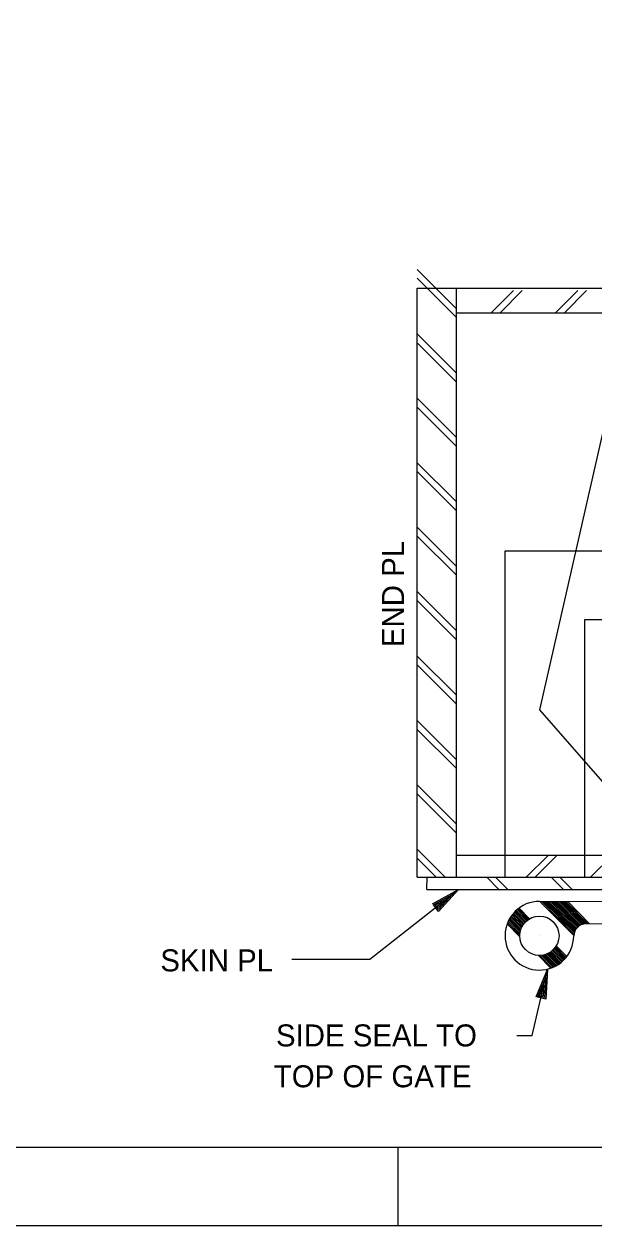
# Model space of a CAD drawing. Extents: x 0.1 to 13.5, y 0.1 to 9.5.
# Drawn here: x 7.414 to 8.625, y 0.125 to 2.675 of the extents above; entities that cross this region are included whole.
import ezdxf

# ---------------------------------------------------------------- set-up
doc = ezdxf.new("R2010")
doc.units = 0
for name, color, linetype in [('Level 0', 7, 'Continuous'), ('Level 1', 7, 'Continuous'), ('Level 13', 7, 'Continuous'), ('Level 25', 7, 'Continuous'), ('Level 3', 7, 'Continuous'), ('Level 50', 7, 'Continuous')]:
    doc.layers.add(name, color=color, linetype=linetype)

msp = doc.modelspace()

# ---------------------------------------------------------------- linework, layer by layer
at = {"layer": 'Level 0'}
for p, q in [((8.3325, 2.0711), (8.2492, 2.1544)), ((8.3325, 2.0522), (8.2492, 2.1356)), ((8.4066, 2.0626), (8.4535, 2.1095)), ((8.4254, 2.0626), (8.4723, 2.1095)), ((8.5433, 2.0626), (8.5902, 2.1095)), ((8.5621, 2.0626), (8.6091, 2.1095)), ((8.3325, 1.9344), (8.2492, 2.0177)), ((8.3325, 1.9155), (8.2492, 1.9989)), ((8.3325, 1.7977), (8.2492, 1.881)), ((8.3325, 1.7788), (8.2492, 1.8622)), ((8.3325, 1.661), (8.2492, 1.7443)), ((8.3325, 1.6421), (8.2492, 1.7255)), ((8.3325, 1.5243), (8.2492, 1.6076)), ((8.3325, 1.5054), (8.2492, 1.5888)), ((8.3325, 1.3876), (8.2492, 1.4709)), ((8.3325, 1.3687), (8.2492, 1.452)), ((8.3325, 1.2509), (8.2492, 1.3342)), ((8.3325, 1.232), (8.2492, 1.3153)), ((8.3325, 1.1141), (8.2492, 1.1975)), ((8.3325, 1.0953), (8.2492, 1.1786)), ((8.3325, 0.9774), (8.2492, 1.0608)), ((8.3325, 0.9586), (8.2492, 1.0419)), ((8.3086, 0.8647), (8.2492, 0.9241)), ((8.2897, 0.8647), (8.2492, 0.9052)), ((8.481, 0.8647), (8.5279, 0.9115)), ((8.4999, 0.8647), (8.5467, 0.9115)), ((8.6177, 0.8647), (8.6646, 0.9115)), ((8.423, 0.8387), (8.397, 0.8647)), ((8.4419, 0.8387), (8.4159, 0.8647)), ((8.5597, 0.8387), (8.5337, 0.8647)), ((8.5786, 0.8387), (8.5526, 0.8647))]:
    msp.add_line(p, q, dxfattribs=at)
at = {"layer": 'Level 1'}
msp.add_line((8.2083, 0.2917), (8.2083, 0.125), dxfattribs=at)
for points in [[(0.125, 9.4583), (13.4583, 9.4583), (13.4583, 0.125), (0.125, 0.125)], [(0.625, 9.2917), (13.2917, 9.2917), (13.2917, 0.2917), (0.625, 0.2917)]]:
    msp.add_lwpolyline(points, close=True, dxfattribs=at)
at = {"layer": 'Level 13'}
for p, q in [((8.4558, 0.7909), (8.4777, 0.7686)), ((8.4577, 0.7927), (8.4796, 0.7704)), ((8.4596, 0.7944), (8.4815, 0.7722)), ((8.4615, 0.7962), (8.4835, 0.7738)), ((8.4635, 0.7979), (8.4857, 0.7754)), ((8.4656, 0.7995), (8.4879, 0.7768)), ((8.9261, 0.8105), (8.5094, 0.8137)), ((8.5101, 0.8136), (8.5818, 0.7409)), ((8.5138, 0.8136), (8.5821, 0.7442)), ((8.5175, 0.8136), (8.5828, 0.7473)), ((8.5211, 0.8136), (8.5838, 0.75)), ((8.5248, 0.8135), (8.5849, 0.7525)), ((8.5285, 0.8135), (8.5861, 0.755)), ((8.5322, 0.8135), (8.588, 0.7569)), ((8.5359, 0.8135), (8.5899, 0.7587)), ((8.5396, 0.8134), (8.5917, 0.7605)), ((8.5432, 0.8134), (8.5939, 0.762)), ((8.5469, 0.8134), (8.5962, 0.7633)), ((8.5506, 0.8133), (8.5988, 0.7644)), ((8.5543, 0.8133), (8.6016, 0.7653)), ((8.558, 0.8133), (8.6047, 0.7658)), ((8.5617, 0.8133), (8.6082, 0.766)), ((8.5653, 0.8132), (8.6118, 0.766)), ((8.569, 0.8132), (8.6155, 0.766)), ((8.4403, 0.7657), (8.4672, 0.7384)), ((8.4414, 0.7684), (8.4672, 0.7422)), ((8.4425, 0.771), (8.4674, 0.7456)), ((8.4437, 0.7735), (8.468, 0.7488)), ((8.445, 0.7759), (8.4687, 0.7518)), ((8.4463, 0.7782), (8.4696, 0.7546)), ((8.4477, 0.7805), (8.4706, 0.7573)), ((8.4492, 0.7827), (8.4718, 0.7598)), ((8.4508, 0.7848), (8.4731, 0.7621)), ((8.4524, 0.7869), (8.4743, 0.7647)), ((8.4541, 0.7889), (8.4761, 0.7665)), ((8.9257, 0.7636), (8.608, 0.766)), ((8.5416, 0.7149), (8.5636, 0.6926)), ((8.5431, 0.717), (8.565, 0.6948)), ((8.5446, 0.7193), (8.5669, 0.6966)), ((8.5059, 0.6992), (8.5328, 0.6719)), ((8.5097, 0.6991), (8.5355, 0.6728)), ((8.5131, 0.6993), (8.5381, 0.6739)), ((8.5163, 0.6997), (8.5406, 0.6751)), ((8.5193, 0.7004), (8.543, 0.6763)), ((8.5221, 0.7012), (8.5454, 0.6776)), ((8.5248, 0.7023), (8.5477, 0.679)), ((8.5273, 0.7034), (8.5499, 0.6805)), ((8.5297, 0.7047), (8.5521, 0.682)), ((8.532, 0.7061), (8.5541, 0.6836)), ((8.5341, 0.7076), (8.5562, 0.6853)), ((8.5362, 0.7092), (8.5581, 0.6869)), ((8.5381, 0.711), (8.56, 0.6888)), ((8.5399, 0.7129), (8.5617, 0.6907))]:
    msp.add_line(p, q, dxfattribs=at)
msp.add_circle((8.5088, 0.7407), 0.0417, dxfattribs=at)
for centre, radius, end in [((8.5088, 0.7407), 0.0729, 359.5648), ((8.6078, 0.74), 0.026, 179.5648)]:
    msp.add_arc(centre, radius, 89.5648, end, dxfattribs=at)
at = {"layer": 'Level 25'}
for p, q in [((8.2492, 0.8647), (8.2492, 2.1147)), ((8.2492, 2.1147), (10.8827, 2.1146)), ((8.3325, 0.8647), (8.3325, 2.1147)), ((8.3325, 2.0626), (10.8827, 2.0626)), ((8.4359, 0.8647), (8.4359, 1.5574)), ((8.4359, 1.5574), (10.8827, 1.5574)), ((8.6053, 0.8647), (8.6053, 1.4116)), ((8.6053, 1.4116), (10.8827, 1.4115)), ((8.3325, 0.9116), (10.8827, 0.9115)), ((8.2492, 0.8647), (10.8827, 0.8647)), ((8.27, 0.8387), (8.2701, 0.8647)), ((8.27, 0.8387), (10.8827, 0.8387)), ((8.5088, 0.7407), (8.5088, 0.7407))]:
    msp.add_line(p, q, dxfattribs=at)
at = {"layer": 'Level 3'}
for p, q in [((8.6653, 1.9059), (8.5089, 1.2203)), ((8.5089, 1.2203), (8.8084, 0.8779)), ((8.1484, 0.6908), (8.3373, 0.8387)), ((7.983, 0.6908), (8.1484, 0.6908)), ((8.5263, 0.6691), (8.5263, 0.6691)), ((8.5224, 0.6523), (8.5224, 0.6523))]:
    msp.add_line(p, q, dxfattribs=at)
for points in [[(8.4606, 0.5288), (8.4935, 0.5288), (8.5263, 0.6691)], [(8.5021, 0.6108), (8.5263, 0.6691), (8.5222, 0.6061), (8.505, 0.6101), (8.5224, 0.6523), (8.5195, 0.6095), (8.5085, 0.612), (8.5186, 0.636), (8.5169, 0.6128), (8.5124, 0.6139), (8.5146, 0.6192)]]:
    msp.add_lwpolyline(points, dxfattribs=at)
at = {"layer": 'Level 50'}
for p, q in [((8.3236, 0.828), (8.3236, 0.828)), ((8.3373, 0.8387), (8.3373, 0.8387))]:
    msp.add_line(p, q, dxfattribs=at)
msp.add_lwpolyline([(8.2818, 0.8084), (8.3373, 0.8387), (8.2946, 0.7921), (8.2837, 0.806), (8.3236, 0.828), (8.2946, 0.7964), (8.2876, 0.8053), (8.3105, 0.8177), (8.2947, 0.8006), (8.2918, 0.8043), (8.2969, 0.807)], dxfattribs=at)

# ---------------------------------------------------------------- texts
at = {"layer": 'Level 25'}
msp.add_text('END PL', height=0.0467, rotation=90, dxfattribs=at).set_placement((8.2211, 1.3529))
for s, height, p in [('SKIN PL', 0.0467, (7.7036, 0.6651)), ('SIDE SEAL TO ', 0.046698, (7.9493, 0.5059)), ('TOP OF GATE', 0.046698, (7.9447, 0.4192))]:
    msp.add_text(s, height=height, dxfattribs=at).set_placement(p)

doc.saveas('drawing.dxf')
